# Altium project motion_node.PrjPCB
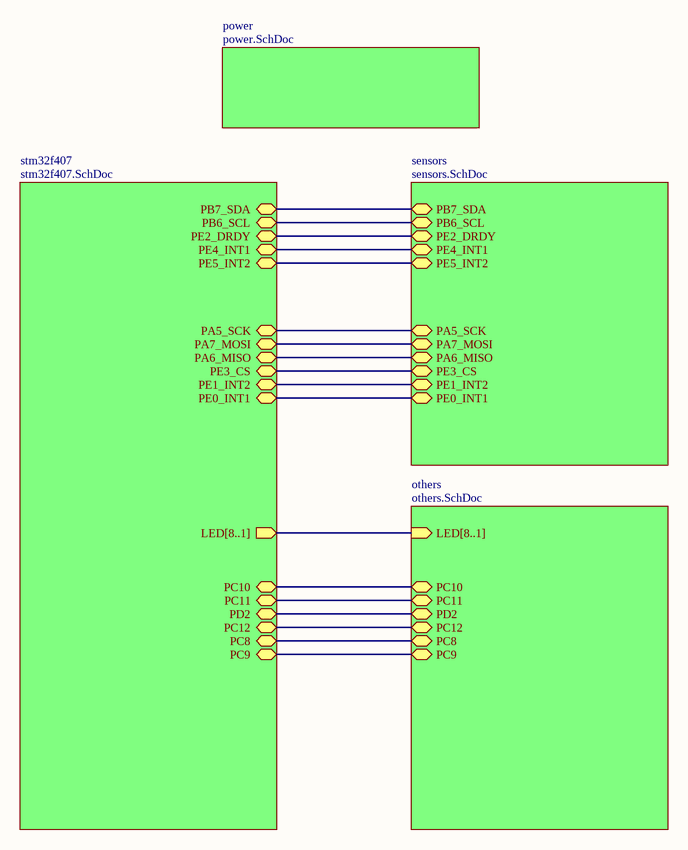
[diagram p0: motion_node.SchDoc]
5 sheets, 90 parts. Net scope: hierarchical (ports join the sheet entries above them; power ports are global).
Board file: motion_node.PcbDoc
Sheets:
  motion_node.SchDoc
    stm32f407 = stm32f407.SchDoc
    sensors = sensors.SchDoc
    others = others.SchDoc
    power = power.SchDoc

## Sheet motion_node.SchDoc
size A4

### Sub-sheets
others = others.SchDoc: LED[8..1] (in), PC10 (bidir), PC11 (bidir), PD2 (bidir), PC12 (bidir), PC8 (bidir), PC9 (bidir)
power = power.SchDoc: no entries
sensors = sensors.SchDoc: PB7_SDA (bidir), PB6_SCL (bidir), PE2_DRDY (bidir), PE4_INT1 (bidir), PE5_INT2 (bidir), PA5_SCK (bidir), PA7_MOSI (bidir), PA6_MISO (bidir), PE3_CS (bidir), PE1_INT2 (bidir), PE0_INT1 (bidir)
stm32f407 = stm32f407.SchDoc: LED[8..1] (out), PC10 (bidir), PC11 (bidir), PD2 (bidir), PC12 (bidir), PC8 (bidir), PC9 (bidir), PB7_SDA (bidir), PB6_SCL (bidir), PE2_DRDY (bidir), PE4_INT1 (bidir), PE5_INT2 (bidir), PA5_SCK (bidir), PA7_MOSI (bidir), PA6_MISO (bidir), PE3_CS (bidir), PE1_INT2 (bidir), PE0_INT1 (bidir)

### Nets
PA5_SCK: sheet stm32f407/PA5_SCK, sheet sensors/PA5_SCK
PA6_MISO: sheet stm32f407/PA6_MISO, sheet sensors/PA6_MISO
PA7_MOSI: sheet stm32f407/PA7_MOSI, sheet sensors/PA7_MOSI
PB6_SCL: sheet stm32f407/PB6_SCL, sheet sensors/PB6_SCL
PB7_SDA: sheet stm32f407/PB7_SDA, sheet sensors/PB7_SDA
PC8: sheet stm32f407/PC8, sheet others/PC8
PC9: sheet stm32f407/PC9, sheet others/PC9
PC10: sheet stm32f407/PC10, sheet others/PC10
PC11: sheet stm32f407/PC11, sheet others/PC11
PC12: sheet stm32f407/PC12, sheet others/PC12
PD2: sheet stm32f407/PD2, sheet others/PD2
PE0_INT1: sheet stm32f407/PE0_INT1, sheet sensors/PE0_INT1
PE1_INT2: sheet stm32f407/PE1_INT2, sheet sensors/PE1_INT2
PE2_DRDY: sheet stm32f407/PE2_DRDY, sheet sensors/PE2_DRDY
PE3_CS: sheet stm32f407/PE3_CS, sheet sensors/PE3_CS
PE4_INT1: sheet stm32f407/PE4_INT1, sheet sensors/PE4_INT1
PE5_INT2: sheet stm32f407/PE5_INT2, sheet sensors/PE5_INT2

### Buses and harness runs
bus sheet others/LED[8..1] = sheet stm32f407/LED[8..1]

## Sheet stm32f407.SchDoc
size A3
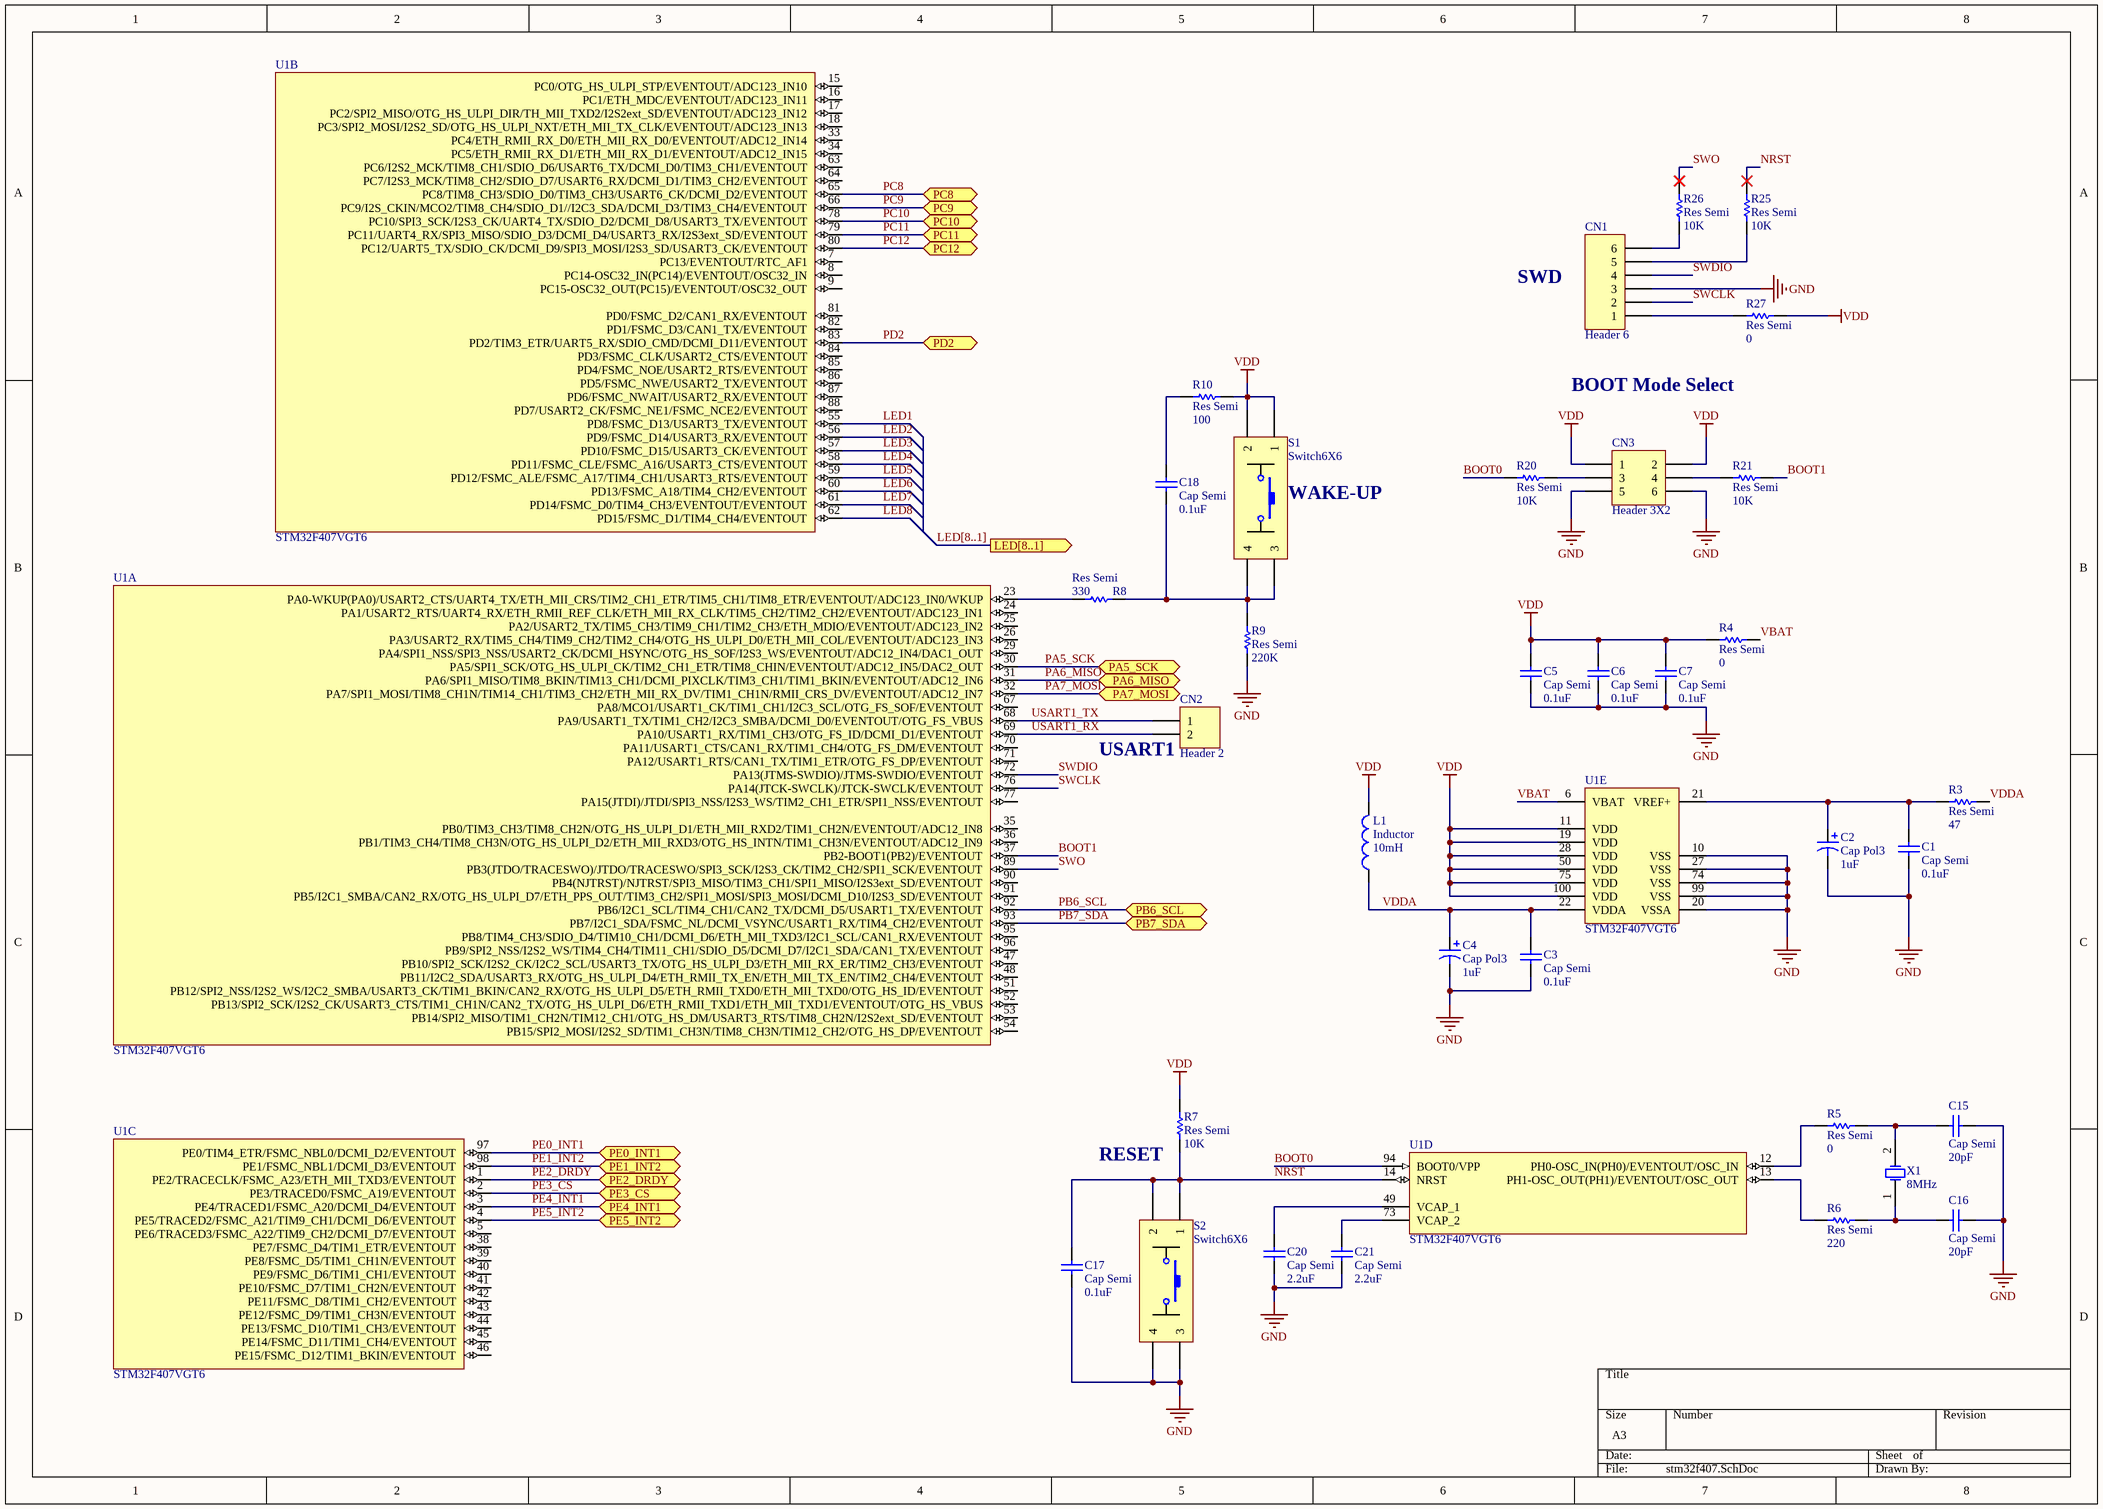
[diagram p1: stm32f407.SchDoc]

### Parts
C1  Cap Semi  value 0.1uF  [C1608-0603]
C2  Cap Pol3  value 1uF  [CC3216-1206]
C3  Cap Semi  value 0.1uF  [C1608-0603]
C4  Cap Pol3  value 1uF  [CC3216-1206]
C5  Cap Semi  value 0.1uF  [C1608-0603]
C6  Cap Semi  value 0.1uF  [C1608-0603]
C7  Cap Semi  value 0.1uF  [C1608-0603]
C15  Cap Semi  value 20pF  [C1608-0603]
C16  Cap Semi  value 20pF  [C1608-0603]
C17  Cap Semi  value 0.1uF  [C1608-0603]
C18  Cap Semi  value 0.1uF  [C1608-0603]
C20  Cap Semi  value 2.2uF  [C1608-0603]
C21  Cap Semi  value 2.2uF  [C1608-0603]
CN1  Header 6  [HDR1X6]
CN2  Header 2  [HDR1X2]
CN3  Header 3X2  [HDR2X3]
L1  Inductor  value 10mH  [R1608-0603]
R3  Res Semi  value 47  [R1608-0603]
R4  Res Semi  value 0  [R1608-0603]
R5  Res Semi  value 0  [R1608-0603]
R6  Res Semi  value 220  [R1608-0603]
R7  Res Semi  value 10K  [R1608-0603]
R8  Res Semi  value 330  [R1608-0603]
R9  Res Semi  value 220K  [R1608-0603]
R10  Res Semi  value 100  [R1608-0603]
R20  Res Semi  value 10K  [R1608-0603]
R21  Res Semi  value 10K  [R1608-0603]
R25  Res Semi  value 10K  [R1608-0603]
R26  Res Semi  value 10K  [R1608-0603]
R27  Res Semi  value 0  [R1608-0603]
S1  Switch6X6  [Switch6X6]
S2  Switch6X6  [Switch6X6]
U1  STM32F407VGT6  [LQFP100_V]  (parts A,B,C,D,E of 5)
X1  8MHz  [XTAL-0.2]

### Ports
LED[8..1] (out), PA5_SCK (bidir), PA6_MISO (bidir), PA7_MOSI (bidir), PB6_SCL (bidir), PB7_SDA (bidir), PC8 (bidir), PC9 (bidir), PC10 (bidir), PC11 (bidir), PC12 (bidir), PD2 (bidir), PE0_INT1 (bidir), PE1_INT2 (bidir), PE2_DRDY (bidir), PE3_CS (bidir), PE4_INT1 (bidir), PE5_INT2 (bidir)

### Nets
GND: C1.1 C2.2 C3.1 C4.2 C5.1 C6.1 C7.1 C15.1 C16.1 C17.2 C20.1 C21.1 CN1.3 CN3.5 CN3.6 R9.1 S2.3 S2.4 U1.10(VSS) U1.20(VSSA) U1.27(VSS) U1.74(VSS) U1.99(VSS)
VDD: C5.2 C6.2 C7.2 CN3.1 CN3.2 L1.2 R4.1 R7.2 R10.1 R27.2 S1.1 S1.2 U1.11(VDD) U1.19(VDD) U1.28(VDD) U1.50(VDD) U1.75(VDD) U1.100(VDD)
BOOT0: R20.2 U1.94(BOOT0/VPP)
BOOT1: R21.1 U1.37(PB2-BOOT1(PB2)/EVENTOUT)
LED1: U1.55(PD8/FSMC_D13/USART3_TX/EVENTOUT)
LED2: U1.56(PD9/FSMC_D14/USART3_RX/EVENTOUT)
LED3: U1.57(PD10/FSMC_D15/USART3_CK/EVENTOUT)
LED4: U1.58(PD11/FSMC_CLE/FSMC_A16/USART3_CTS/EVENTOUT)
LED5: U1.59(PD12/FSMC_ALE/FSMC_A17/TIM4_CH1/USART3_RTS/EVENTOUT)
LED6: U1.60(PD13/FSMC_A18/TIM4_CH2/EVENTOUT)
LED7: U1.61(PD14/FSMC_D0/TIM4_CH3/EVENTOUT/EVENTOUT)
LED8: U1.62(PD15/FSMC_D1/TIM4_CH4/EVENTOUT)
NRST: C17.1 R7.1 R25.1 S2.1 S2.2 U1.14(NRST)
PA5_SCK: U1.30(PA5/SPI1_SCK/OTG_HS_ULPI_CK/TIM2_CH1_ETR/TIM8_CHIN/EVENTOUT/ADC12_IN5/DAC2_OUT) ; port PA5_SCK
PA6_MISO: U1.31(PA6/SPI1_MISO/TIM8_BKIN/TIM13_CH1/DCMI_PIXCLK/TIM3_CH1/TIM1_BKIN/EVENTOUT/ADC12_IN6) ; port PA6_MISO
PA7_MOSI: U1.32(PA7/SPI1_MOSI/TIM8_CH1N/TIM14_CH1/TIM3_CH2/ETH_MII_RX_DV/TIM1_CH1N/RMII_CRS_DV/EVENTOUT/ADC12_IN7) ; port PA7_MOSI
PB6_SCL: U1.92(PB6/I2C1_SCL/TIM4_CH1/CAN2_TX/DCMI_D5/USART1_TX/EVENTOUT) ; port PB6_SCL
PB7_SDA: U1.93(PB7/I2C1_SDA/FSMC_NL/DCMI_VSYNC/USART1_RX/TIM4_CH2/EVENTOUT) ; port PB7_SDA
PC8: U1.65(PC8/TIM8_CH3/SDIO_D0/TIM3_CH3/USART6_CK/DCMI_D2/EVENTOUT) ; port PC8
PC9: U1.66(PC9/I2S_CKIN/MCO2/TIM8_CH4/SDIO_D1//I2C3_SDA/DCMI_D3/TIM3_CH4/EVENTOUT) ; port PC9
PC10: U1.78(PC10/SPI3_SCK/I2S3_CK/UART4_TX/SDIO_D2/DCMI_D8/USART3_TX/EVENTOUT) ; port PC10
PC11: U1.79(PC11/UART4_RX/SPI3_MISO/SDIO_D3/DCMI_D4/USART3_RX/I2S3ext_SD/EVENTOUT) ; port PC11
PC12: U1.80(PC12/UART5_TX/SDIO_CK/DCMI_D9/SPI3_MOSI/I2S3_SD/USART3_CK/EVENTOUT) ; port PC12
PD2: U1.83(PD2/TIM3_ETR/UART5_RX/SDIO_CMD/DCMI_D11/EVENTOUT) ; port PD2
PE0_INT1: U1.97(PE0/TIM4_ETR/FSMC_NBL0/DCMI_D2/EVENTOUT) ; port PE0_INT1
PE1_INT2: U1.98(PE1/FSMC_NBL1/DCMI_D3/EVENTOUT) ; port PE1_INT2
PE2_DRDY: U1.1(PE2/TRACECLK/FSMC_A23/ETH_MII_TXD3/EVENTOUT) ; port PE2_DRDY
PE3_CS: U1.2(PE3/TRACED0/FSMC_A19/EVENTOUT) ; port PE3_CS
PE4_INT1: U1.3(PE4/TRACED1/FSMC_A20/DCMI_D4/EVENTOUT) ; port PE4_INT1
PE5_INT2: U1.4(PE5/TRACED2/FSMC_A21/TIM9_CH1/DCMI_D6/EVENTOUT) ; port PE5_INT2
SWCLK: CN1.2 U1.76(PA14(JTCK-SWCLK)/JTCK-SWCLK/EVENTOUT)
SWDIO: CN1.4 U1.72(PA13(JTMS-SWDIO)/JTMS-SWDIO/EVENTOUT)
SWO: R26.1 U1.89(PB3(JTDO/TRACESWO)/JTDO/TRACESWO/SPI3_SCK/I2S3_CK/TIM2_CH2/SPI1_SCK/EVENTOUT)
USART1_RX: CN2.2 U1.69(PA10/USART1_RX/TIM1_CH3/OTG_FS_ID/DCMI_D1/EVENTOUT)
USART1_TX: CN2.1 U1.68(PA9/USART1_TX/TIM1_CH2/I2C3_SMBA/DCMI_D0/EVENTOUT/OTG_FS_VBUS)
VBAT: R4.2 U1.6(VBAT)
VDDA: C3.2 C4.1 L1.1 R3.2 U1.22(VDDA)
NetC1_2: C1.2 C2.1 R3.1 U1.21(VREF+)
NetC15_2: C15.2 R5.2 X1.2(OSC2)
NetC16_2: C16.2 R6.2 X1.1(OSC1)
NetC18_1: C18.1 R10.2
NetC18_2: C18.2 R8.1 R9.2 S1.3 S1.4
NetC20_2: C20.2 U1.49(VCAP_1)
NetC21_2: C21.2 U1.73(VCAP_2)
NetCN1_1: CN1.1 R27.1
NetCN1_5: CN1.5 R25.2
NetCN1_6: CN1.6 R26.2
NetCN3_3: CN3.3 R20.1
NetCN3_4: CN3.4 R21.2
NetR5_1: R5.1 U1.12(PH0-OSC_IN(PH0)/EVENTOUT/OSC_IN)
NetR6_1: R6.1 U1.13(PH1-OSC_OUT(PH1)/EVENTOUT/OSC_OUT)
NetR8_2: R8.2 U1.23(PA0-WKUP(PA0)/USART2_CTS/UART4_TX/ETH_MII_CRS/TIM2_CH1_ETR/TIM5_CH1/TIM8_ETR/EVENTOUT/ADC123_IN0/WKUP)

Not connected (* = marked no-connect by the designer): U1 5(PE6/TRACED3/FSMC_A22/TIM9_CH2/DCMI_D7/EVENTOUT) 7(PC13/EVENTOUT/RTC_AF1) 8(PC14-OSC32_IN(PC14)/EVENTOUT/OSC32_IN) 9(PC15-OSC32_OUT(PC15)/EVENTOUT/OSC32_OUT) 15(PC0/OTG_HS_ULPI_STP/EVENTOUT/ADC123_IN10) 16(PC1/ETH_MDC/EVENTOUT/ADC123_IN11) 17(PC2/SPI2_MISO/OTG_HS_ULPI_DIR/TH_MII_TXD2/I2S2ext_SD/EVENTOUT/ADC123_IN12) 18(PC3/SPI2_MOSI/I2S2_SD/OTG_HS_ULPI_NXT/ETH_MII_TX_CLK/EVENTOUT/ADC123_IN13) 24(PA1/USART2_RTS/UART4_RX/ETH_RMII_REF_CLK/ETH_MII_RX_CLK/TIM5_CH2/TIM2_CH2/EVENTOUT/ADC123_IN1) 25(PA2/USART2_TX/TIM5_CH3/TIM9_CH1/TIM2_CH3/ETH_MDIO/EVENTOUT/ADC123_IN2) 26(PA3/USART2_RX/TIM5_CH4/TIM9_CH2/TIM2_CH4/OTG_HS_ULPI_D0/ETH_MII_COL/EVENTOUT/ADC123_IN3) 29(PA4/SPI1_NSS/SPI3_NSS/USART2_CK/DCMI_HSYNC/OTG_HS_SOF/I2S3_WS/EVENTOUT/ADC12_IN4/DAC1_OUT) 33(PC4/ETH_RMII_RX_D0/ETH_MII_RX_D0/EVENTOUT/ADC12_IN14) 34(PC5/ETH_RMII_RX_D1/ETH_MII_RX_D1/EVENTOUT/ADC12_IN15) 35(PB0/TIM3_CH3/TIM8_CH2N/OTG_HS_ULPI_D1/ETH_MII_RXD2/TIM1_CH2N/EVENTOUT/ADC12_IN8) 36(PB1/TIM3_CH4/TIM8_CH3N/OTG_HS_ULPI_D2/ETH_MII_RXD3/OTG_HS_INTN/TIM1_CH3N/EVENTOUT/ADC12_IN9) 38(PE7/FSMC_D4/TIM1_ETR/EVENTOUT) 39(PE8/FSMC_D5/TIM1_CH1N/EVENTOUT) 40(PE9/FSMC_D6/TIM1_CH1/EVENTOUT) 41(PE10/FSMC_D7/TIM1_CH2N/EVENTOUT) 42(PE11/FSMC_D8/TIM1_CH2/EVENTOUT) 43(PE12/FSMC_D9/TIM1_CH3N/EVENTOUT) 44(PE13/FSMC_D10/TIM1_CH3/EVENTOUT) 45(PE14/FSMC_D11/TIM1_CH4/EVENTOUT) 46(PE15/FSMC_D12/TIM1_BKIN/EVENTOUT) 47(PB10/SPI2_SCK/I2S2_CK/I2C2_SCL/USART3_TX/OTG_HS_ULPI_D3/ETH_MII_RX_ER/TIM2_CH3/EVENTOUT) 48(PB11/I2C2_SDA/USART3_RX/OTG_HS_ULPI_D4/ETH_RMII_TX_EN/ETH_MII_TX_EN/TIM2_CH4/EVENTOUT) 51(PB12/SPI2_NSS/I2S2_WS/I2C2_SMBA/USART3_CK/TIM1_BKIN/CAN2_RX/OTG_HS_ULPI_D5/ETH_RMII_TXD0/ETH_MII_TXD0/OTG_HS_ID/EVENTOUT) 52(PB13/SPI2_SCK/I2S2_CK/USART3_CTS/TIM1_CH1N/CAN2_TX/OTG_HS_ULPI_D6/ETH_RMII_TXD1/ETH_MII_TXD1/EVENTOUT/OTG_HS_VBUS) 53(PB14/SPI2_MISO/TIM1_CH2N/TIM12_CH1/OTG_HS_DM/USART3_RTS/TIM8_CH2N/I2S2ext_SD/EVENTOUT) 54(PB15/SPI2_MOSI/I2S2_SD/TIM1_CH3N/TIM8_CH3N/TIM12_CH2/OTG_HS_DP/EVENTOUT) 63(PC6/I2S2_MCK/TIM8_CH1/SDIO_D6/USART6_TX/DCMI_D0/TIM3_CH1/EVENTOUT) 64(PC7/I2S3_MCK/TIM8_CH2/SDIO_D7/USART6_RX/DCMI_D1/TIM3_CH2/EVENTOUT) 67(PA8/MCO1/USART1_CK/TIM1_CH1/I2C3_SCL/OTG_FS_SOF/EVENTOUT) 70(PA11/USART1_CTS/CAN1_RX/TIM1_CH4/OTG_FS_DM/EVENTOUT) 71(PA12/USART1_RTS/CAN1_TX/TIM1_ETR/OTG_FS_DP/EVENTOUT) 77(PA15(JTDI)/JTDI/SPI3_NSS/I2S3_WS/TIM2_CH1_ETR/SPI1_NSS/EVENTOUT) 81(PD0/FSMC_D2/CAN1_RX/EVENTOUT) 82(PD1/FSMC_D3/CAN1_TX/EVENTOUT) 84(PD3/FSMC_CLK/USART2_CTS/EVENTOUT) 85(PD4/FSMC_NOE/USART2_RTS/EVENTOUT) 86(PD5/FSMC_NWE/USART2_TX/EVENTOUT) 87(PD6/FSMC_NWAIT/USART2_RX/EVENTOUT) 88(PD7/USART2_CK/FSMC_NE1/FSMC_NCE2/EVENTOUT) 90(PB4(NJTRST)/NJTRST/SPI3_MISO/TIM3_CH1/SPI1_MISO/I2S3ext_SD/EVENTOUT) 91(PB5/I2C1_SMBA/CAN2_RX/OTG_HS_ULPI_D7/ETH_PPS_OUT/TIM3_CH2/SPI1_MOSI/SPI3_MOSI/DCMI_D10/I2S3_SD/EVENTOUT) 95(PB8/TIM4_CH3/SDIO_D4/TIM10_CH1/DCMI_D6/ETH_MII_TXD3/I2C1_SCL/CAN1_RX/EVENTOUT) 96(PB9/SPI2_NSS/I2S2_WS/TIM4_CH4/TIM11_CH1/SDIO_D5/DCMI_D7/I2C1_SDA/CAN1_TX/EVENTOUT)

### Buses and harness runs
bus LED[8..1] = port LED[8..1]

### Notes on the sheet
- SWD
- BOOT Mode Select
- (near S1) WAKE-UP
- (near CN2) USART1
- (near R7) RESET

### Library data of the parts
C1 C3 C5-C7 C15-C18 C20 C21 = Cap Semi: Capacitor (Semiconductor SIM Model)
C2 C4 = Cap Pol3: Polarized Capacitor (Surface Mount)
CN1 = Header 6: Header, 6-Pin
CN2 = Header 2: Header, 2-Pin
CN3 = Header 3X2: Header, 3-Pin, Dual row
L1 = Inductor: Code_IEC: 1005
R3-R10 R20 R21 R25-R27 = Res Semi: Semiconductor Resistor
S1 S2 = Switch6X6: Switch
X1 = XTAL: Crystal Oscillator

## Sheet sensors.SchDoc
size A4
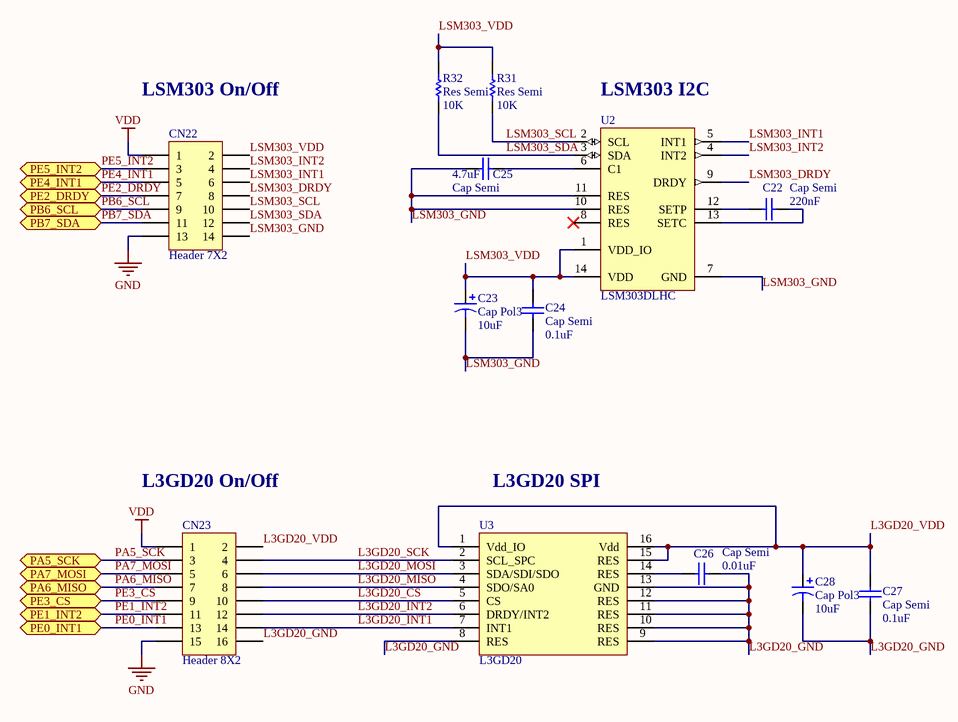
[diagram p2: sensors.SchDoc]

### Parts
C22  Cap Semi  value 220nF  [C1608-0603]
C23  Cap Pol3  value 10uF  [CC3216-1206]
C24  Cap Semi  value 0.1uF  [C1608-0603]
C25  Cap Semi  value 4.7uF  [C1608-0603]
C26  Cap Semi  value 0.01uF  [C1608-0603]
C27  Cap Semi  value 0.1uF  [C1608-0603]
C28  Cap Pol3  value 10uF  [CC3216-1206]
CN22  Header 7X2  [HDR2X7]
CN23  Header 8X2  [HDR2X8]
R31  Res Semi  value 10K  [R1608-0603]
R32  Res Semi  value 10K  [R1608-0603]
U2  LSM303DLHC  [LGA14-3X5X1_N]
U3  L3GD20  [LGA16-4X4X1]

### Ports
PA5_SCK (bidir), PA6_MISO (bidir), PA7_MOSI (bidir), PB6_SCL (bidir), PB7_SDA (bidir), PE0_INT1 (bidir), PE1_INT2 (bidir), PE2_DRDY (bidir), PE3_CS (bidir), PE4_INT1 (bidir), PE5_INT2 (bidir)

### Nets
GND: CN22.13 CN23.15
VDD: CN22.1 CN23.1
L3GD20_CS: CN23.10 U3.5(CS)
L3GD20_GND: C26.1 C27.2 C28.2 CN23.16 U3.8(RES) U3.9(RES) U3.10(RES) U3.11(RES) U3.12(RES) U3.13(GND)
L3GD20_INT1: CN23.14 U3.7(INT1)
L3GD20_INT2: CN23.12 U3.6(DRDY/INT2)
L3GD20_MISO: CN23.8 U3.4(SDO/SA0)
L3GD20_MOSI: CN23.6 U3.3(SDA/SDI/SDO)
L3GD20_SCK: CN23.4 U3.2(SCL_SPC)
L3GD20_VDD: C27.1 C28.1 CN23.2 U3.1(Vdd_IO) U3.15(RES) U3.16(Vdd)
LSM303_DRDY: CN22.8 U2.9(DRDY)
LSM303_GND: C23.2 C24.2 C25.2 CN22.14 U2.7(GND) U2.10(RES) U2.11(RES)
LSM303_INT1: CN22.6 U2.5(INT1)
LSM303_INT2: CN22.4 U2.4(INT2)
LSM303_SCL: CN22.10 R31.2 U2.2(SCL)
LSM303_SDA: CN22.12 R32.2 U2.3(SDA)
LSM303_VDD: C23.1 C24.1 CN22.2 R31.1 R32.1 U2.1(VDD_IO) U2.14(VDD)
PA5_SCK: CN23.3 ; port PA5_SCK
PA6_MISO: CN23.7 ; port PA6_MISO
PA7_MOSI: CN23.5 ; port PA7_MOSI
PB6_SCL: CN22.9 ; port PB6_SCL
PB7_SDA: CN22.11 ; port PB7_SDA
PE0_INT1: CN23.13 ; port PE0_INT1
PE1_INT2: CN23.11 ; port PE1_INT2
PE2_DRDY: CN22.7 ; port PE2_DRDY
PE3_CS: CN23.9 ; port PE3_CS
PE4_INT1: CN22.5 ; port PE4_INT1
PE5_INT2: CN22.3 ; port PE5_INT2
NetC22_1: C22.1 U2.13(SETC)
NetC22_2: C22.2 U2.12(SETP)
NetC25_1: C25.1 U2.6(C1)
NetC26_2: C26.2 U3.14(RES)

Not connected (* = marked no-connect by the designer): U2 8(RES)*

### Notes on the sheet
- LSM303 On/Off
- (near U2) LSM303 I2C
- L3GD20 On/Off
- L3GD20 SPI

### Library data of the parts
C22 C24-C27 = Cap Semi: Capacitor (Semiconductor SIM Model)
C23 C28 = Cap Pol3: Polarized Capacitor (Surface Mount)
CN22 = Header 7X2: Header, 7-Pin, Dual row
CN23 = Header 8X2: Header, 8-Pin, Dual row
R31 R32 = Res Semi: Semiconductor Resistor

## Sheet others.SchDoc
size A4
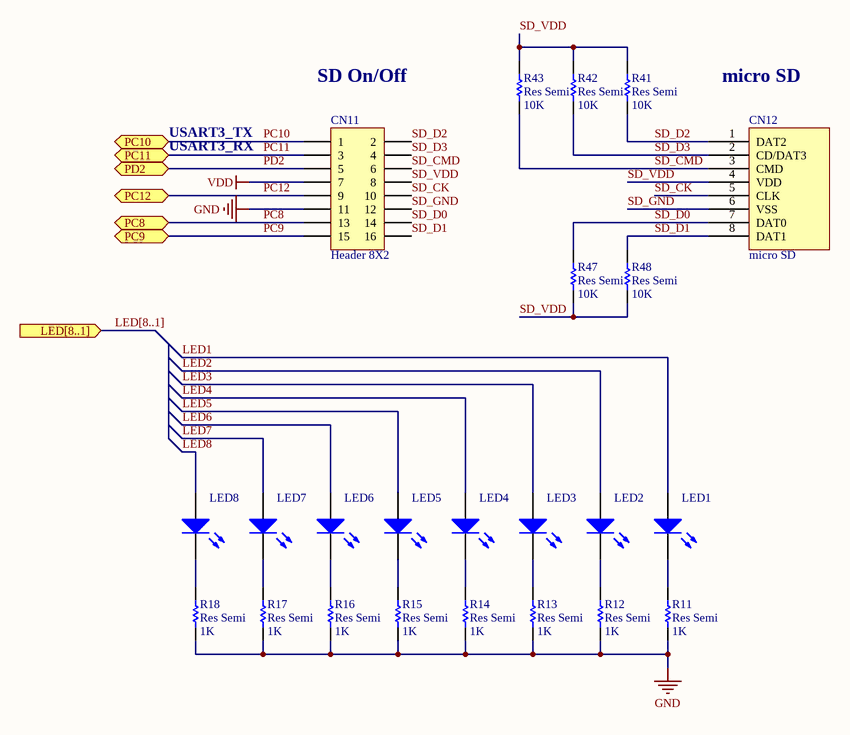
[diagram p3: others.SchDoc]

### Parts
CN11  Header 8X2  [HDR2X8]
CN12  micro SD  [micro SD]
LED1  (no value)  [D1608-0603]
LED2  (no value)  [D1608-0603]
LED3  (no value)  [D1608-0603]
LED4  (no value)  [D1608-0603]
LED5  (no value)  [D1608-0603]
LED6  (no value)  [D1608-0603]
LED7  (no value)  [D1608-0603]
LED8  (no value)  [D1608-0603]
R11  Res Semi  value 1K  [R1608-0603]
R12  Res Semi  value 1K  [R1608-0603]
R13  Res Semi  value 1K  [R1608-0603]
R14  Res Semi  value 1K  [R1608-0603]
R15  Res Semi  value 1K  [R1608-0603]
R16  Res Semi  value 1K  [R1608-0603]
R17  Res Semi  value 1K  [R1608-0603]
R18  Res Semi  value 1K  [R1608-0603]
R41  Res Semi  value 10K  [R1608-0603]
R42  Res Semi  value 10K  [R1608-0603]
R43  Res Semi  value 10K  [R1608-0603]
R47  Res Semi  value 10K  [R1608-0603]
R48  Res Semi  value 10K  [R1608-0603]

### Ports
LED[8..1] (in), PC8, PC9 (bidir), PC10 (bidir), PC11 (bidir), PC12 (bidir), PD2 (bidir)

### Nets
GND: CN11.11 R11.2 R12.2 R13.2 R14.2 R15.2 R16.2 R17.2 R18.2
VDD: CN11.7
LED1: LED1.1(A)
LED2: LED2.1(A)
LED3: LED3.1(A)
LED4: LED4.1(A)
LED5: LED5.1(A)
LED6: LED6.1(A)
LED7: LED7.1(A)
LED8: LED8.1(A)
PC8: CN11.13 ; port PC8
PC9: CN11.15 ; port PC9
PC10: CN11.1 ; port PC10
PC11: CN11.3 ; port PC11
PC12: CN11.9 ; port PC12
PD2: CN11.5 ; port PD2
SD_CK: CN11.10 CN12.5(CLK)
SD_CMD: CN11.6 CN12.3(CMD) R43.2
SD_D0: CN11.14 CN12.7(DAT0) R47.1
SD_D1: CN11.16 CN12.8(DAT1) R48.1
SD_D2: CN11.2 CN12.1(DAT2) R41.2
SD_D3: CN11.4 CN12.2(CD/DAT3) R42.2
SD_GND: CN11.12 CN12.6(VSS)
SD_VDD: CN11.8 CN12.4(VDD) R41.1 R42.1 R43.1 R47.2 R48.2
NetLED1_2: LED1.2(K) R11.1
NetLED2_2: LED2.2(K) R12.1
NetLED3_2: LED3.2(K) R13.1
NetLED4_2: LED4.2(K) R14.1
NetLED5_2: LED5.2(K) R15.1
NetLED6_2: LED6.2(K) R16.1
NetLED7_2: LED7.2(K) R17.1
NetLED8_2: LED8.2(K) R18.1

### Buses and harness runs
bus LED[8..1] = port LED[8..1]

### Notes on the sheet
- SD On/Off
- micro SD
- USART3_TX
- USART3_RX

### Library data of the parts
CN11 = Header 8X2: Header, 8-Pin, Dual row
LED1-LED8 = LED2: Typical RED, GREEN, YELLOW, AMBER GaAs LED
R11-R18 R41-R43 R47 R48 = Res Semi: Semiconductor Resistor

## Sheet power.SchDoc
size A4
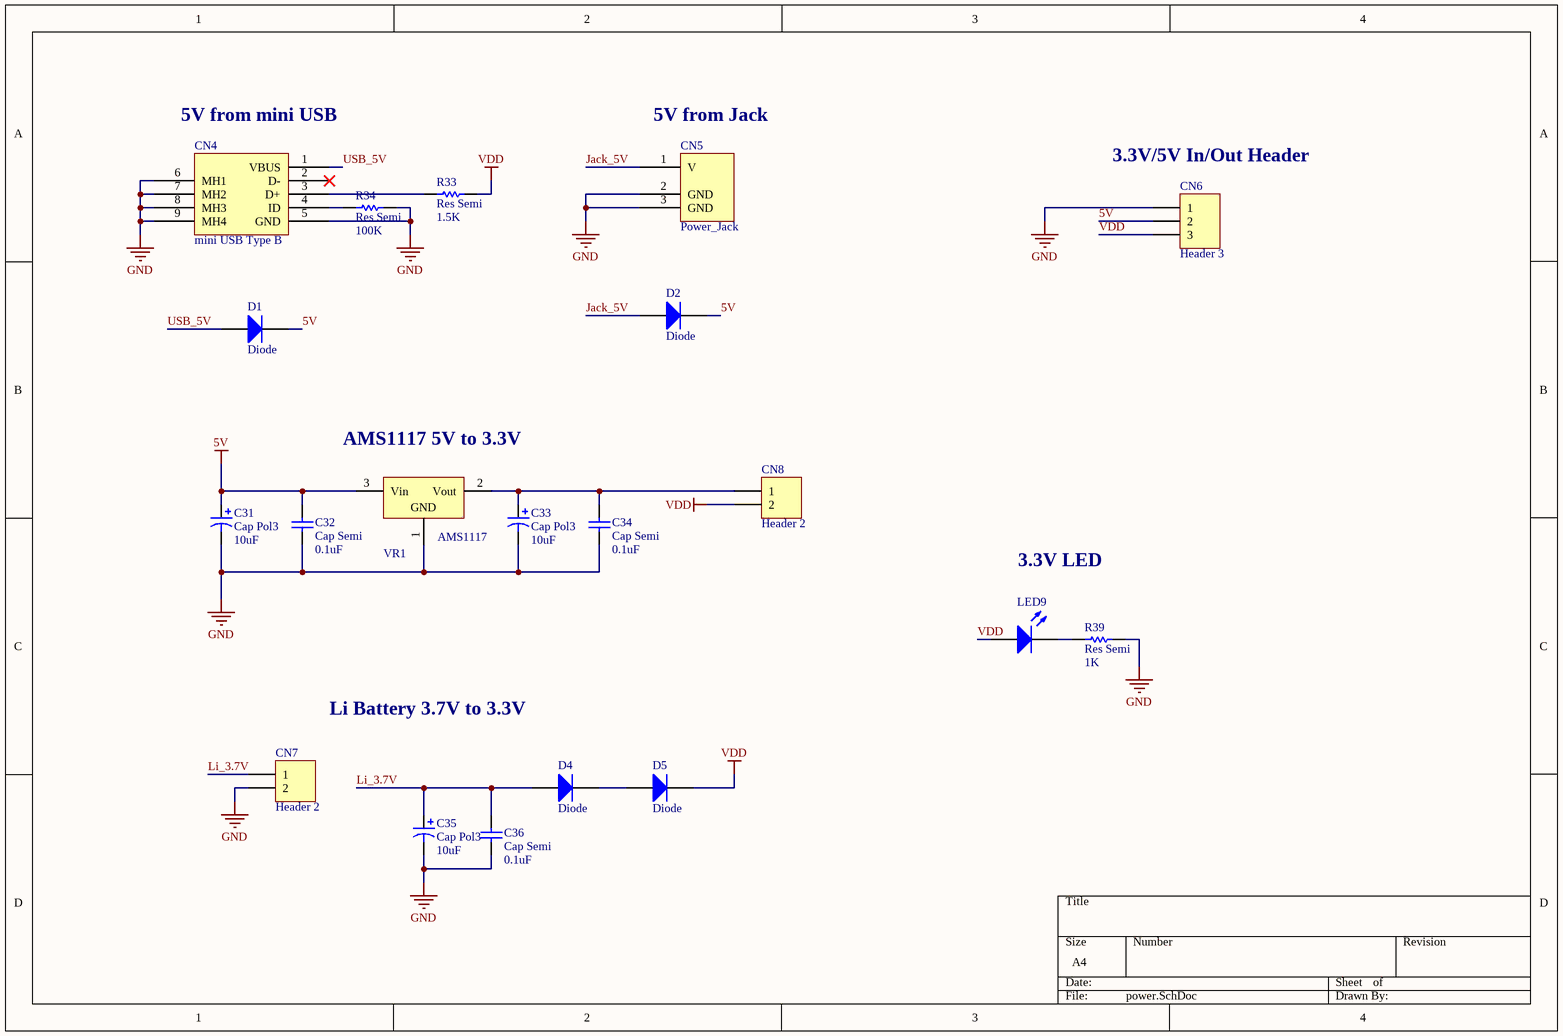
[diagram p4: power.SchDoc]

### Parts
C31  Cap Pol3  value 10uF  [CC3216-1206]
C32  Cap Semi  value 0.1uF  [C1608-0603]
C33  Cap Pol3  value 10uF  [CC3216-1206]
C34  Cap Semi  value 0.1uF  [C1608-0603]
C35  Cap Pol3  value 10uF  [CC3216-1206]
C36  Cap Semi  value 0.1uF  [C1608-0603]
CN4  mini USB Type B  [mini USB Type B]
CN5  Power_Jack  [POWER_JACK]
CN6  Header 3  [HDR1X3]
CN7  Header 2  [HDR1X2]
CN8  Header 2  [HDR1X2]
D1  Diode  [IN5817]
D2  Diode  [IN5817]
D4  Diode  [IN5817]
D5  Diode  [IN5817]
LED9  (no value)  [D1608-0603]
R33  Res Semi  value 1.5K  [R1608-0603]
R34  Res Semi  value 100K  [R1608-0603]
R39  Res Semi  value 1K  [R1608-0603]
VR1  AMS1117  [AMS1117]

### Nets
5V: C31.1 C32.2 CN6.2 D1.2(K) D2.2(K) VR1.3(Vin)
GND: C31.2 C32.1 C33.2 C34.1 C35.2 C36.1 CN4.5(GND) CN4.6(MH1) CN4.7(MH2) CN4.8(MH3) CN4.9(MH4) CN5.2(GND) CN5.3(GND) CN6.1 CN7.2 R34.1 R39.2 VR1.1(GND)
VDD: CN6.3 CN8.2 D5.2(K) LED9.1(A) R33.1
Jack_5V: CN5.1(V) D2.1(A)
Li_3.7V: C35.1 C36.2 CN7.1 D4.1(A)
USB_5V: CN4.1(VBUS) D1.1(A)
NetC33_1: C33.1 C34.2 CN8.1 VR1.2(Vout)
NetCN4_3: CN4.3(D+) R33.2
NetCN4_4: CN4.4(ID) R34.2
NetD4_2: D4.2(K) D5.1(A)
NetLED9_2: LED9.2(K) R39.1

Not connected (* = marked no-connect by the designer): CN4 2(D-)*

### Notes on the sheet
- (near CN4) 5V from mini USB
- (near CN5) 5V from Jack
- (near CN6) 3.3V/5V In/Out Header
- (near VR1) AMS1117 5V to 3.3V
- 3.3V LED
- Li Battery 3.7V to 3.3V

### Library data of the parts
C31 C33 C35 = Cap Pol3: Polarized Capacitor (Surface Mount)
C32 C34 C36 = Cap Semi: Capacitor (Semiconductor SIM Model)
CN6 = Header 3: Header, 3-Pin
CN7 CN8 = Header 2: Header, 2-Pin
D1 D2 D4 D5 = Diode: Default Diode
LED9 = LED2: as LED1 on sheet others
R33 R34 R39 = Res Semi: Semiconductor Resistor
VR1 = AMS1117: Voltage Regulator; Code - JEDEC: SMD-220

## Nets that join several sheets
GND: stm32f407 (23 pins), sensors (CN22.13 CN23.15), others (9 pins), power (18 pins)
VDD: stm32f407 (18 pins), sensors (CN22.1 CN23.1), others (CN11.7), power (5 pins)
LED1: stm32f407 (U1.55), others (LED1.1)
LED2: stm32f407 (U1.56), others (LED2.1)
LED3: stm32f407 (U1.57), others (LED3.1)
LED4: stm32f407 (U1.58), others (LED4.1)
LED5: stm32f407 (U1.59), others (LED5.1)
LED6: stm32f407 (U1.60), others (LED6.1)
LED7: stm32f407 (U1.61), others (LED7.1)
LED8: stm32f407 (U1.62), others (LED8.1)
PA5_SCK: stm32f407 (U1.30), sensors (CN23.3)
PA6_MISO: stm32f407 (U1.31), sensors (CN23.7)
PA7_MOSI: stm32f407 (U1.32), sensors (CN23.5)
PB6_SCL: stm32f407 (U1.92), sensors (CN22.9)
PB7_SDA: stm32f407 (U1.93), sensors (CN22.11)
PC8: stm32f407 (U1.65), others (CN11.13)
PC9: stm32f407 (U1.66), others (CN11.15)
PC10: stm32f407 (U1.78), others (CN11.1)
PC11: stm32f407 (U1.79), others (CN11.3)
PC12: stm32f407 (U1.80), others (CN11.9)
PD2: stm32f407 (U1.83), others (CN11.5)
PE0_INT1: stm32f407 (U1.97), sensors (CN23.13)
PE1_INT2: stm32f407 (U1.98), sensors (CN23.11)
PE2_DRDY: stm32f407 (U1.1), sensors (CN22.7)
PE3_CS: stm32f407 (U1.2), sensors (CN23.9)
PE4_INT1: stm32f407 (U1.3), sensors (CN22.5)
PE5_INT2: stm32f407 (U1.4), sensors (CN22.3)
